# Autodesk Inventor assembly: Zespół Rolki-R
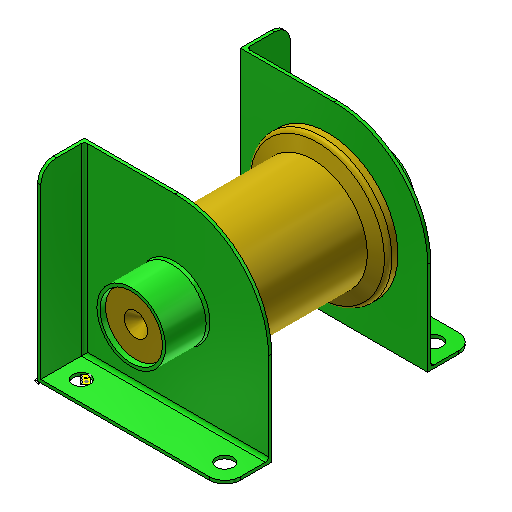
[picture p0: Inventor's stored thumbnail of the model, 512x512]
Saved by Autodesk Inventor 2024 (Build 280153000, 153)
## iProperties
Company: ATC
Created: 2023-03
Part Number: Zespół Rolki-R
Document SubType Name: Assembly
Designer: Andrzej Jaskulski
Checked By: A.J.
Engr Approved By: Andrzej Jaskulski
Mfg Approved By: Andrzej Jaskulski
Authority: A.J.
Title: A.J.: Kurs R2024-MEP
Author: Andrzej Jaskulski
Revision Number: 1/24
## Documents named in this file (4)
- C:\Users\AndJas\Documents\R2024-MEP\Obszar roboczy\SPEC\GOTOWE\Zespół Rolki-R.iam
- C:\Users\AndJas\Documents\R2024-MEP\Obszar roboczy\SPEC\GOTOWE\Podpora-RP.ipt
- C:\Users\AndJas\Documents\R2024-MEP\Obszar roboczy\SPEC\GOTOWE\Podpora-RL.ipt
- C:\Users\AndJas\Documents\R2024-MEP\Obszar roboczy\SPEC\GOTOWE\Rolka-R.ipt
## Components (3 placed, 3 different names)
1. Podpora-RP:1 — Równoległy:1, Równoległy:2, Zestawiający:1, Wstaw:1
2. Podpora-RL:1 — Równoległy:1, Równoległy:2, Zestawiający:1, Wstaw:2
3. Rolka-R:1 — Wstaw:1, Wstaw:2
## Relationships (5: Flush 2, Insert 2, Mate 1)
- Równoległy:1 [Flush]: Podpora-RP:1 ↔ Podpora-RL:1
- Równoległy:2 [Flush]: Podpora-RP:1 ↔ Podpora-RL:1
- Zestawiający:1 [Mate]: Podpora-RP:1 ↔ Podpora-RL:1
- Wstaw:1 [Insert]: Podpora-RP:1 ↔ Rolka-R:1
- Wstaw:2 [Insert]: Podpora-RL:1 ↔ Rolka-R:1
